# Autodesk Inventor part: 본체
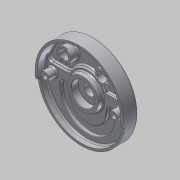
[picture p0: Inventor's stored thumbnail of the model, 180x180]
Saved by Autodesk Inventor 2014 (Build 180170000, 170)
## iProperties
Created: 2015-06
Part Number: 본체
Material: 알루미늄 6061
Document SubType Name: Modeling
Designer: MYHOME
Mass: 1071.24 g
Surface Area: 1023.76 cm^2
Volume: 395.292 cm^3
Density: 2.71 g/cm^3
Appearance: 알루미늄 - 평지
Author: MYHOME
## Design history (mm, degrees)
sketch "스케치3"
  geometry: C1 r 95 at (0, 0); 1 further point
  constraints: 1 centre point, 1 coincident
  dimensions: "d0" = 190 diameter of C1
extrude "돌출1" new body sketch "스케치3" distance "d1" = 32; taper "d2" = 0 deg
sketch "스케치9"
  geometry: C1 r 95 at (0, 0) reference; C2 r 90 at (0, 0)
  constraints: 1 centre point, 1 coincident
  dimensions: "d19" = 180 diameter of C2
extrude "돌출5" cut sketch "스케치9" distance "d20" = 25; taper "d21" = 0 deg
sketch "스케치10"
  geometry: L1 (-75.657, 16)-(-45.033, 16); L2 (38.833, 16)-(75.657, 16); A1 r 90 centre (0, 0) between (-88.566, 16) and (88.566, 16) reference; A2 r 90 centre (0, 0) between (-88.566, 16) and (88.566, 16); A3 r 90 centre (0, 0) between (85.114, 29.25) and (-85.114, 29.25); A4 r 42 centre (0, 0) between (38.833, 16) and (-36.373, 21); A5 r 10 centre (-45.033, 26) between (-45.033, 16) and (-36.373, 21); A6 r 10 centre (-75.657, 26) between (-85.114, 29.25) and (-75.657, 16); A7 r 10 centre (75.657, 26) between (75.657, 16) and (85.114, 29.25); 2 further points
  constraints: 18 point on circle, 6 centre point, 6 tangent, 4 end point, 4 equal radius, 3 point on line, 2 horizontal, 1 coincident
  dimensions: "d28" = 16 distance from line of A1.centre L1; "d31" = 10 radius of A5
extrude "돌출8" join sketch "스케치10" distance "d32" = 7; taper "d33" = 0 deg
sketch "스케치12"
  geometry: L1 (-45.033, 16)-(-75.657, 16) reference; L2 (-50, -19)-(-50, -14); L3 (50, -19)-(50, -14); L4 (-59, -19)-(-59, -14); L5 (-41, -19)-(-41, -14); L6 (41, -19)-(41, -14); L7 (59, -19)-(59, -14); A1 r 42 centre (0, 0) between (38.833, 16) and (-36.373, 21) reference; A2 r 50 centre (0, -19) between (-50, -19) and (50, -19); A3 r 59 centre (0, -19) between (-59, -19) and (59, -19); A4 r 41 centre (0, -19) between (-41, -19) and (41, -19); A5 r 9 centre (-50, -19) between (-41, -19) and (-59, -19); A6 r 9 centre (50, -19) between (59, -19) and (41, -19); A7 r 9 centre (50, -14) between (41, -14) and (41, -14); A8 r 9 centre (-50, -14) between (-59, -14) and (-41, -14); 1 further point
  constraints: 16 point on circle, 12 end point, 10 tangent, 7 centre point, 3 parallel, 2 coincident, 2 horizontal alignment, 1 perpendicular, 1 vertical alignment
  dimensions: "d34" = 19 distance of A2.centre A1.centre; "d35" = 41 radius of A4; "d36" = 18 radial gap between concentric circles of A3 A4; "d37" = 5 distance of L2.start L2.end; "d38" = 5 distance of L3.start L3.end; "d39" = 18 diameter of A7; "d40" = 18 diameter of A8
extrude "돌출9" cut sketch "스케치12" distance "d41" = 7; taper "d42" = 0 deg
sketch "스케치13"
  geometry: C1 r 35 at (0, 0); A1 r 90 centre (0, 0) between (-85.114, 29.25) and (85.114, 29.25) reference
  constraints: 1 centre point, 1 coincident
  dimensions: "d43" = 70 diameter of C1
extrude "돌출10" join sketch "스케치13" distance "d44" = 10; taper "d45" = -10 deg
sketch "스케치14"
  geometry: L1 (38.833, 16)-(75.657, 16) reference; L2 (-79.505, 52)-(79.505, 52); C1 r 15 at (40, 52); C2 r 15 at (-40, 52); A1 r 42 centre (0, 0) between (38.833, 16) and (-36.373, 21) reference; A2 r 95 centre (0, 0) between (-79.505, 52) and (79.505, 52) reference
  constraints: 2 centre point, 2 end point, 2 point on circle, 2 point on line, 1 parallel
  dimensions: "d46" = 52 distance from line of A1.centre L2; "d47" = 30 diameter of C1; "d48" = 30 diameter of C2; "d49" = 40 horizontal distance of C1.centre A1.centre; "d50" = 80 distance of C2.centre C1.centre
extrude "돌출11" join sketch "스케치14" distance "d51" = 18; taper "d52" = 0 deg
sketch "스케치15"
  geometry: C1 r 15 at (0, 0) reference; C2 r 15 at (-80, 0) reference; C3 r 10 at (0, 0); C4 r 10 at (-80, 0); 1 further point
  constraints: 2 centre point, 2 coincident
  dimensions: "d53" = 20 diameter of C3; "d54" = 20 diameter of C4
extrude "돌출12" cut sketch "스케치15" stored distance "d55" = 18; taper "d56" = 0 deg
sketch "스케치16"
  geometry: L1 (-13.748, 6)-(13.748, 6); L2 (-13.748, -6)-(13.748, -6); L3 (-86, 13.748)-(-86, -13.748); L4 (-74, 13.748)-(-74, -13.748); C1 r 10 at (0, 0) reference; C2 r 10 at (-80, 0) reference; A1 r 15 centre (0, 0) between (-13.748, 6) and (13.748, 6) reference; A2 r 15 centre (-80, 0) between (-86, 13.748) and (-86, -13.748) reference; 1 further point
  constraints: 8 end point, 8 point on circle, 2 parallel, 1 horizontal, 1 perpendicular
  dimensions: "d57" = 6 distance from line of L1 C1.centre; "d58" = 12 distance of L2.start L1.start; "d61" = 6 horizontal distance of L3.start C2.centre; "d62" = 12 distance of L3.start L4.start
extrude "돌출13" cut sketch "스케치16" distance "d59" = 3; taper "d60" = 0 deg
extrude "돌출14" cut sketch "스케치16" distance "d63" = 3; taper "d64" = 0 deg
sketch "스케치17"
  geometry: C1 r 33.237 at (0, 0) reference; C2 r 25 at (0, 0)
  constraints: 1 centre point, 1 coincident
  dimensions: "d65" = 50 diameter of C2
extrude "돌출15" cut sketch "스케치17" distance "d66" = 15; taper "d67" = 0 deg
sketch "스케치18"
  geometry: C1 r 25 at (0, 0) reference; C2 r 11.5 at (0, 0)
  constraints: 1 centre point, 1 coincident
  dimensions: "d68" = 23 diameter of C2
extrude "돌출16" cut sketch "스케치18" distance "d69" = 15; taper "d70" = 0 deg
sketch "스케치19"
  geometry: C1 r 95 at (0, 0) reference; C2 r 26 at (0, 0)
  constraints: 1 centre point, 1 coincident
  dimensions: "d71" = 52 diameter of C2
extrude "돌출17" join sketch "스케치19" distance "d72" = 15; taper "d73" = -15 deg
sketch "스케치20"
  geometry: C1 r 11.5 at (0, 0) reference
extrude "돌출18" cut sketch "스케치20" stored distance "d74" = 15; taper "d75" = 0 deg
sketch "스케치21"
  geometry: C1 r 35 at (0, 0) reference; C2 r 9 at (-74, 0); C3 r 9 at (74, 0)
  constraints: 2 centre point, 2 horizontal alignment
  dimensions: "d76" = 18 diameter of C2; "d77" = 18 diameter of C3; "d79" = 74 distance of C1.centre C3.centre; "d80" = 148 distance of C2.centre C3.centre
extrude "돌출19" join sketch "스케치21" distance "d81" = 18; taper "d82" = 0 deg
sketch "스케치22"
  geometry: C1 r 9 at (0, 0) reference; C2 r 5.5 at (0, 0); C3 r 9 at (-148, 0) reference; C4 r 5.5 at (-148, 0); 1 further point
  constraints: 2 centre point, 2 coincident
  dimensions: "d83" = 11 diameter of C2; "d84" = 11 diameter of C4
extrude "돌출20" cut sketch "스케치22" stored distance "d85" = 18; taper "d86" = 0 deg
sketch "스케치23"
  geometry: C1 r 5.5 at (74, 0) reference; C2 r 5.5 at (-74, 0) reference; C3 r 9 at (74, 0); C4 r 9 at (-74, 0)
  constraints: 2 centre point, 2 coincident
  dimensions: "d87" = 18 diameter of C3; "d88" = 18 diameter of C4
extrude "돌출21" cut sketch "스케치23" distance "d89" = 11; taper "d90" = 0 deg
sketch "스케치24"
  geometry: L1 (-95, 0)-(95, 0); L2 (0, 0)-(-94.075, -13.221); L3 (0, 0)-(94.075, -13.221); A1 r 90 centre (0, 0) between (-89.124, -12.526) and (89.124, -12.526) reference; A2 r 95 centre (0, 0) between (-95, 0) and (95, 0) reference; A3 r 90 centre (0, 0) between (-89.124, -12.526) and (89.124, -12.526); A4 r 95 centre (0, 0) between (-94.075, -13.221) and (94.075, -13.221)
  constraints: 10 point on circle, 6 end point, 2 centre point, 2 concentric, 2 midpoint, 2 point on line, 1 horizontal
  dimensions: "d91" = 8 deg angle of L3 L1; "d92" = 8 deg angle of L1 L2
extrude "돌출22" cut sketch "스케치24" distance "d93" = 5; taper "d94" = 0 deg
fillet "모깎기1" dims "d95" = 3
chamfer "모따기1" distance "d96" = 1; stored, may be unused: second distance "d97" = 2, angle "d98" = 45 deg
fillet "모깎기2" dims "d99" = 0.3
sketch "스케치25"
  geometry: C1 r 28.302 at (0, 0) reference; C2 r 68 at (0, 0)
  constraints: 1 centre point, 1 coincident, 1 other
  dimensions: "d100" = 136 diameter of C2
feature "엠보싱1" sketch "스케치25" dims "d101" = 0.5, "d102" = 0
chamfer "모따기2" distance "d103" = 1; stored, may be unused: second distance "d104" = 2, angle "d105" = 45 deg
fillet "모깎기3" dims "d106" = 1
fillet "모깎기4" dims "d107" = 3
fillet "모깎기5" dims "d108" = 3
node "솔리드1"
